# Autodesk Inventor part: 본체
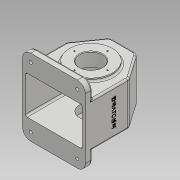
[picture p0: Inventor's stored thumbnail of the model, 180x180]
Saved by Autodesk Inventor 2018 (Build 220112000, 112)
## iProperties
Created: 2022-12
Part Number: 본체
Material: 일반
Document SubType Name: Modeling
Designer: home
Density: 1 g/cm^3
Appearance: 기본값
Author: home
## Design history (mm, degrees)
sketch "스케치1"
  geometry: L1 (-55, -38.5)-(55, -38.5); L2 (55, -38.5)-(55, 38.5); L3 (55, 38.5)-(-55, 38.5); L4 (-55, 38.5)-(-55, -38.5); L5 (-55, -38.5)-(55, 38.5); L6 (55, -38.5)-(-55, 38.5); L7 (-55, 38.5)-(-23.491, 83.5); L8 (-23.491, 83.5)-(23.491, 83.5); L9 (23.491, 83.5)-(55, 38.5); 1 further point
  constraints: 18 end point, 2 horizontal, 2 midpoint, 2 parallel, 1 equal length, 1 perpendicular
  dimensions: "d0" = 110 distance of L3.end L2.end; "d1" = 77 distance of L2.end L1.end; "d2" = 122 distance between parallel lines of L1 L8; "d3" = 35 deg angle of L4 L7
extrude "돌출1" new body sketch "스케치1" distance "d4" = 77; taper "d5" = 0 deg
fillet "모깎기1" dims "d6" = 10
fillet "모깎기2" dims "d7" = 3
feature "쉘1" dims "d8" = 5
sketch "스케치2"
  geometry: L1 (2, 72)-(102, 72) reference; L2 (0, 0)-(104, 0) reference; L3 (107, 3)-(107, 74) reference; L4 (0, 77)-(104, 77) reference; L5 (-3, 3)-(-3, 74) reference; L6 (102, 5)-(102, 72) reference; L7 (102, 72)-(2, 72) reference; L8 (2, 72)-(2, 5) reference; L9 (2, 5)-(102, 5) reference; L10 (0, 77)-(104, 77) reference; L11 (107, 74)-(107, 3) reference; L12 (104, 0)-(0, 0) reference; L13 (-3, 3)-(-3, 74) reference; L14 (33.715, 77)-(70.285, 77) reference; L15 (52, 77)-(52, 0); L16 (11, 105.5)-(93, 105.5); L17 (107, 91.5)-(107, -14.5); L18 (93, -28.5)-(11, -28.5); L19 (-3, -14.5)-(-3, 91.5); L20 (-3, 105.5)-(107, -28.5); L21 (107, 105.5)-(-3, -28.5); A1 r 3 centre (0, 3) between (-3, 3) and (0, 0) reference; A2 r 3 centre (104, 3) between (104, 0) and (107, 3) reference; A3 r 3 centre (104, 74) between (107, 74) and (104, 77) reference; A4 r 3 centre (0, 74) between (0, 77) and (-3, 74) reference; A5 r 3 centre (0, 74) between (0, 77) and (-3, 74) reference; A6 r 3 centre (104, 74) between (107, 74) and (104, 77) reference; A7 r 3 centre (104, 3) between (104, 0) and (107, 3) reference; A8 r 3 centre (0, 3) between (-3, 3) and (0, 0) reference; A9 r 14 centre (93, 91.5) between (107, 91.5) and (93, 105.5); A10 r 14 centre (93, -14.5) between (93, -28.5) and (107, -14.5); A11 r 14 centre (11, -14.5) between (-3, -14.5) and (11, -28.5); A12 r 14 centre (11, 91.5) between (11, 105.5) and (-3, 91.5); 1 further point
  constraints: 14 end point, 8 point on circle, 8 point on line, 8 tangent, 4 centre point, 4 midpoint, 3 equal radius, 2 parallel, 2 perpendicular, 1 horizontal
  dimensions: "d9" = 134 distance of L21.start L20.end; "d10" = 110 distance of L20.end L21.end; "d11" = 14 radius of A9
extrude "돌출2" join sketch "스케치2" distance "d12" = 12; taper "d13" = 0 deg
node "작업 평면1"
sketch "스케치5"
  geometry: L1 (-50, -38.5)-(50, -38.5) reference; L2 (0, -38.5)-(0, 26.5); C1 r 20 at (0, 26.5); 1 further point
  constraints: 2 end point, 1 centre point, 1 coincident, 1 midpoint, 1 vertical
  dimensions: "d14" = 65 distance of L2.start L2.end; "d15" = 40 diameter of C1
extrude "돌출3" cut sketch "스케치5" extent not by distance; stored distance "d16" = 5; taper "d17" = 0 deg
sketch "스케치6"
  geometry: L1 (2, 11.153)-(2, -28.847) reference; L2 (2, -8.847)-(69, -8.847); L3 (69, -28.847)-(69, 11.153) reference; L4 (16, -8.847)-(16, -28.847); L5 (2, 0)-(2, -73.847) reference; L6 (16, -28.847)-(-8, -28.847); L7 (-8, -28.847)-(-8, -46.347); L8 (-8, -46.347)-(-3, -46.347); L9 (-3, -61.847)-(-3, 0) reference; L10 (-3, -46.347)-(2, -46.347); L11 (2, -49.847)-(2, -46.347); L12 (-3, 4.015)-(-3, 42.168) reference; L13 (2, -49.847)-(16, -35.847); L14 (16, -35.847)-(16, -28.847); 1 further point
  constraints: 18 end point, 6 point on line, 4 perpendicular, 2 midpoint, 2 vertical, 1 horizontal
  dimensions: "d18" = 40 diameter of L6 L2; "d20" = 24 distance between parallel lines of L7 L4; "d21" = 5 distance between parallel lines of L12 L7; "d22" = 75 diameter of L8 L2; "d23" = 54 diameter of L13.end L2; "d24" = 135 deg angle of L5 L13
revolve "회전1" sketch "스케치6" stored, may be unused: angle "d25" = 90 deg
sketch "스케치7"
  geometry: C1 r 20 at (0, 26.5) reference; C2 r 31 at (0, 26.5); 1 further point
  constraints: 1 centre point, 1 coincident
  dimensions: "d26" = 62 diameter of C2
extrude "돌출4" join sketch "스케치7" distance "d27" = 10; taper "d28" = 0 deg
sketch "스케치8"
  geometry: C1 r 6 at (18.285, -35.5); 1 further point
  constraints: 1 centre point, 1 vertical alignment
  dimensions: "d29" = 12 diameter of C1; "d30" = 38.5 distance of point (18.285, 3) C1.centre
extrude "돌출5" join sketch "스케치8" distance "d31" = 4; taper "d32" = 0 deg
sketch "스케치9" dims "d33" = 58
  geometry: C1 r 37.5 at (0, 0) reference; C2 r 20 at (0, 0) reference; 3 further points
  constraints: 2 vertical alignment, 1 coincident, 2 other
hole "구멍1" sketch "스케치9" at (0, 29) diameter "d34" = 2.459; stored, may be unused: countersink angle "d38" = 82 deg, drill point angle "d40" = 118 deg; dims "d35" = 6, "d36" = 3.023, "d37" = 2, "d39" = 8
sketch "스케치10" dims "d41" = 52
  geometry: C1 r 20 at (0, 0) reference; C2 r 31 at (0, 0) reference; 3 further points
  constraints: 2 vertical alignment, 1 coincident, 2 other
hole "구멍2" sketch "스케치10" at (0, 26) diameter "d42" = 2.459; stored, may be unused: countersink angle "d46" = 82 deg, drill point angle "d48" = 118 deg; dims "d43" = 6, "d44" = 3.023, "d45" = 2, "d47" = 8
hole "구멍3" diameter "d51" = 5.188; stored, may be unused: countersink angle "d55" = 82 deg, drill point angle "d57" = 118 deg; dims "d52" = 20, "d53" = 3.023, "d54" = 2, "d56" = 16, "d58" = 10, "d59" = 10
sketch "스케치11"
  geometry: L1 (102, -72)-(102, -5) reference; L2 (102, -5)-(2, -5) reference; L3 (2, -5)-(2, -72) reference; L4 (2, -72)-(102, -72) reference; L5 (0, 0)-(104, 0) reference; L6 (107, 14.5)-(107, -3) reference; L7 (11, 28.5)-(93, 28.5) reference; L8 (-3, -3)-(-3, 14.5) reference; L9 (-3, -74)-(-3, -3) reference; L10 (104, -77)-(0, -77) reference; L11 (107, -74)-(107, -91.5) reference; L12 (93, -105.5)-(11, -105.5) reference; L13 (-3, -91.5)-(-3, -74) reference; L14 (107, -3)-(107, -74) reference; A1 r 14 centre (11, -91.5) between (-3, -91.5) and (11, -105.5) reference; A2 r 14 centre (93, -91.5) between (93, -105.5) and (107, -91.5) reference; A3 r 3 centre (0, -3) between (0, 0) and (-3, -3) reference; A4 r 3 centre (104, -3) between (107, -3) and (104, 0) reference; A5 r 14 centre (93, 14.5) between (107, 14.5) and (93, 28.5) reference; A6 r 14 centre (11, 14.5) between (11, 28.5) and (-3, 14.5) reference; A7 r 3 centre (0, -74) between (-3, -74) and (0, -77) reference; A8 r 3 centre (104, -74) between (104, -77) and (107, -74) reference; A9 r 14 centre (93, -91.5) between (93, -105.5) and (107, -91.5) reference; A10 r 14 centre (11, -91.5) between (-3, -91.5) and (11, -105.5) reference; 1 further point
hole "구멍4" sketch "스케치11" at (11, -91.5), (93, -91.5), (93, 14.5), (11, 14.5) diameter "d63" = 5.5; stored, may be unused: countersink angle "d67" = 82 deg, drill point angle "d69" = 118 deg; dims "d64" = 12, "d65" = 15, "d66" = 2, "d68" = 16
chamfer "모따기1" distance "d70" = 1; stored, may be unused: second distance "d71" = 2, angle "d72" = 45 deg
fillet "모깎기3" dims "d73" = 3
fillet "모깎기4" dims "d74" = 3
fillet "모깎기5" dims "d75" = 3
fillet "모깎기6" dims "d76" = 3
fillet "모깎기7" dims "d77" = 3
sketch "스케치12"
  geometry: L1 (88.5, -73.847)-(-17.5, -73.847) reference; L2 (-3, 0)-(-3, -58.847) reference; 2 further points
  constraints: 1 other
  dimensions: "d78" = 50 distance from line of L1 point (35.5, -23.847); "d79" = 38.5 distance from line of L2 point (35.5, -23.847)
feature "엠보싱1" sketch "스케치12" dims "d0" = 110, "d1" = 77, "d2" = 122, "d3" = 35 deg, "d80" = 0.5, "d81" = 0
node "솔리드1"
pattern_circular "원형 패턴1" dims angle "d61" = 360 deg
node "절단 모서리 투영1"
node "절단 모서리 투영3"
